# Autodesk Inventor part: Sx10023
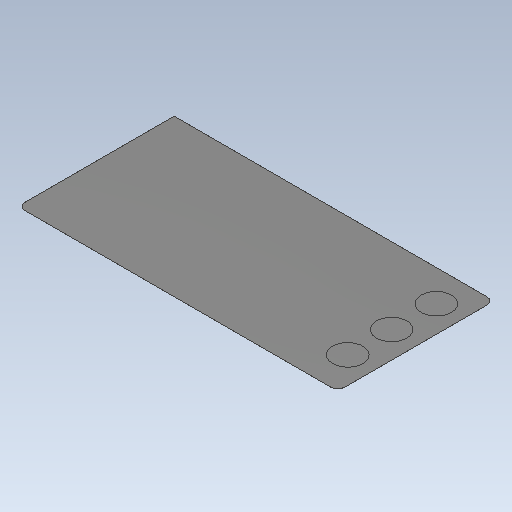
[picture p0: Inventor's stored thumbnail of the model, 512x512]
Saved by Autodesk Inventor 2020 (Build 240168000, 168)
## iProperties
Created: 2021-02
Part Number: Sx10023
Material: Generico
Document SubType Name: Modeling
Designer: zambolin
Density: 1 g/cm^3
Appearance: Default
Author: zambolin
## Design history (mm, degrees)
feature "Solido2"
node "Solido1"
